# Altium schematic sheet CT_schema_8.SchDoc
size 274 x 160 mm
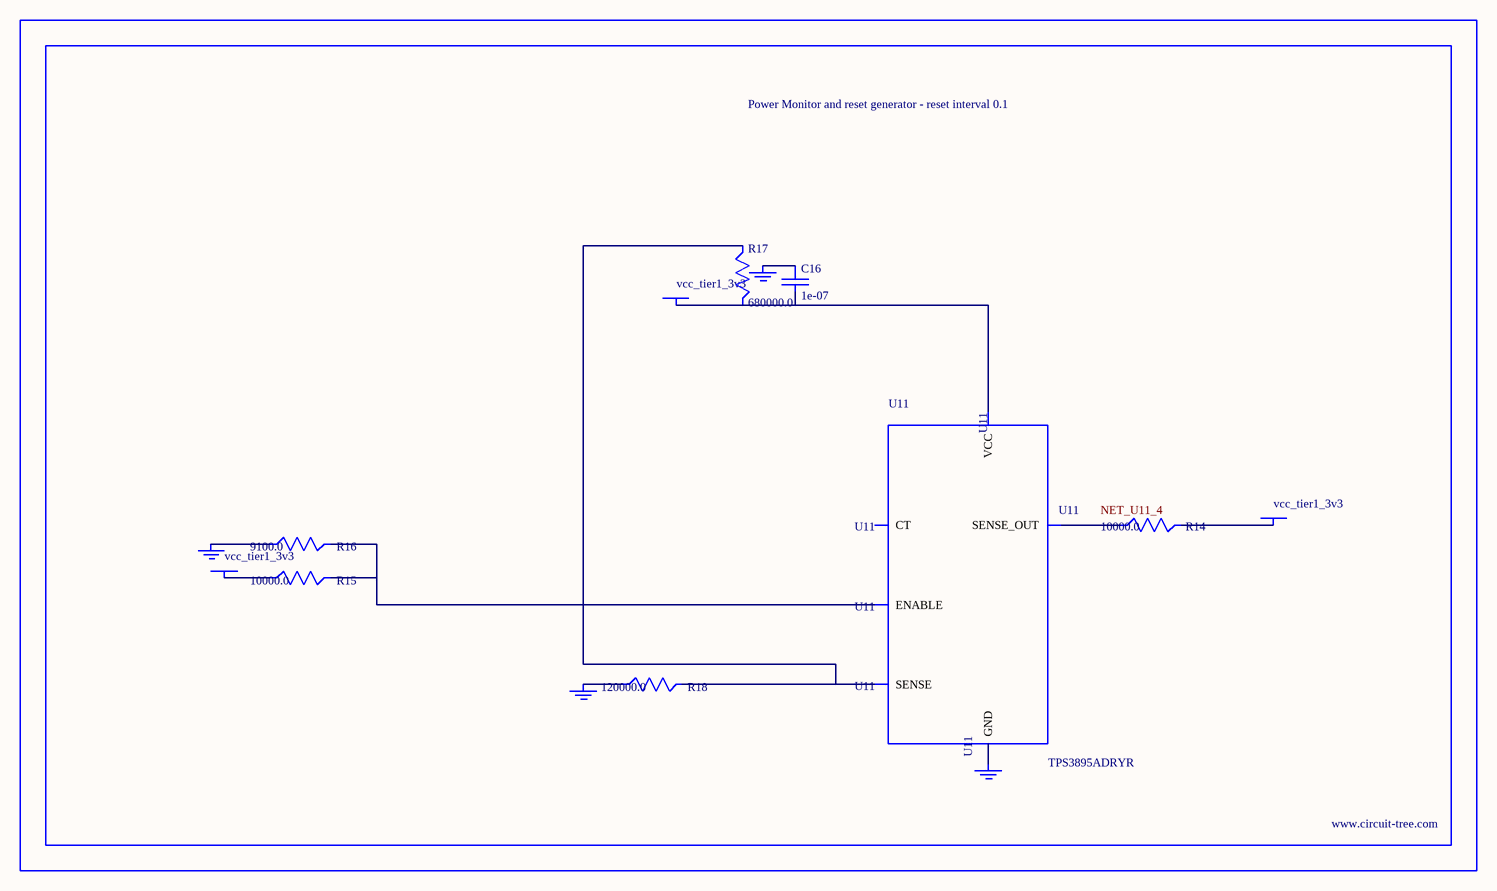
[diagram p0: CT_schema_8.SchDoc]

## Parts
BORDER7  (no value)
C16  1e-07  [C0402]
GND_INSTANCE_7_0  (no value)
GND_INSTANCE_7_1  (no value)
GND_INSTANCE_7_2  (no value)
GND_INSTANCE_7_3  (no value)
POWER_INSTANCE_7_0  vcc_tier1_3v3
POWER_INSTANCE_7_1  vcc_tier1_3v3
POWER_INSTANCE_7_2  vcc_tier1_3v3
R14  10000.0  [R0603]
R15  10000.0  [R0603]
R16  9100.0  [R0603]
R17  680000.0  [R0603]
R18  120000.0  [R0603]
U11  TPS3895ADRYR  [SON-6]

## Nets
NetC16_1: C16.1 GND_INSTANCE_7_2.0(GND)
NetC16_2: C16.2 POWER_INSTANCE_7_2.0(PWR) R17.2 U11.6(VCC)
NetGND_INSTANCE_7_0_0: GND_INSTANCE_7_0.0(GND) R16.1
NetGND_INSTANCE_7_1_0: GND_INSTANCE_7_1.0(GND) R18.1
NetGND_INSTANCE_7_3_0: GND_INSTANCE_7_3.0(GND) U11.2(GND)
NetPOWER_INSTANCE_7_0_0: POWER_INSTANCE_7_0.0(PWR) R15.1
NetPOWER_INSTANCE_7_1_0: POWER_INSTANCE_7_1.0(PWR) R14.2
NetR14_1: R14.1 U11.4(SENSE_OUT)
NetR15_2: R15.2 R16.2 U11.1(ENABLE)
NetR17_1: R17.1 R18.2 U11.3(SENSE)

Not connected (* = marked no-connect by the designer): U11 5(CT)

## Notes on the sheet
- Labels drawn without touching a wire or pin: NET_U11_4

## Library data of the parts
BORDER7 = BORDER_PAGE7
C16 = C0402C104K3RACTU
GND_INSTANCE_7_0-GND_INSTANCE_7_3 = GND
POWER_INSTANCE_7_0-POWER_INSTANCE_7_2 = PWR
R14 R15 = RC0603JR-0710KL
R16 = RC0603JR-079K1L
R17 = RC0603JR-07680KL
R18 = RC0603JR-07120KL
